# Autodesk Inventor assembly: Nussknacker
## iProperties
Shininess: 64.0
Length Units: 11269
Angle Units: 11279
Time Units: 11290
Mass Units: 11283
Length Display Precision: 3
Angle Display Precision: 2
Compacted: True
Created: 2005-08
Part Number: Nussknacker
Document SubType Name: Assembly
Designer: Kumpf
Density: 0.0
Volumn: 0.0
Area: 0.0
PropertySet Name: Model Information
Control State: 0
Master: False
Checked Out: False
Author: Kumpf
